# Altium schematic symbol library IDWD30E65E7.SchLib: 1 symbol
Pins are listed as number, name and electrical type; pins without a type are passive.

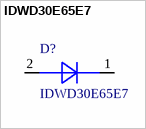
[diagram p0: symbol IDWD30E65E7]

## IDWD30E65E7
designator D?
Standard Diode Symbol, 2 Leads, 1 Cathode, 2 Anode; Manufacturer: Infineon Technologies
pins: 1 Cathode, 2 Anode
